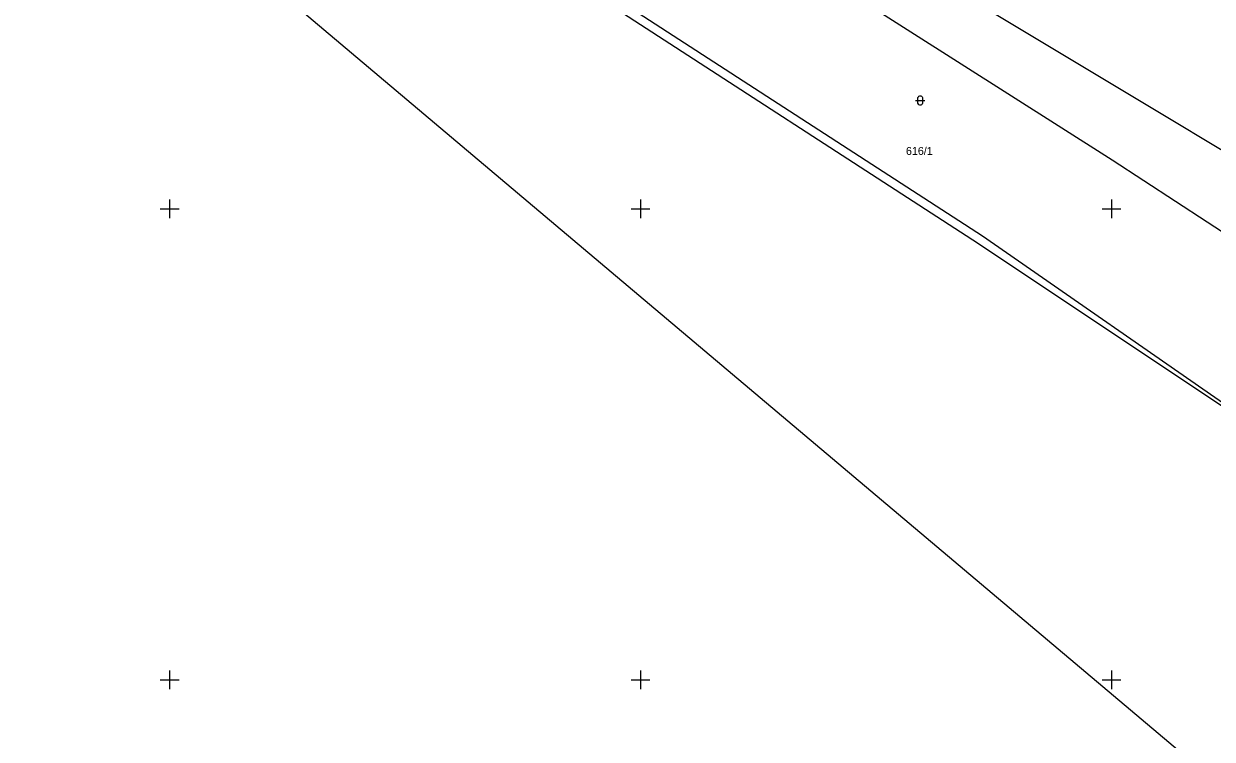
# Model space of a CAD drawing. Extents: x -492379 to -491966, y -1126153 to -1125860.
# Drawn here: x -492309.3 to -492233.6, y -1125993.8 to -1125948.2 of the extents above; entities that cross this region are included whole.
import ezdxf

# ---------------------------------------------------------------- set-up
doc = ezdxf.new("R2010")
doc.units = 0
doc.layers.add('katastrální mapa', color=7, linetype='Continuous')
doc.layers.add('síť', color=7, linetype='Continuous')

msp = doc.modelspace()

# ---------------------------------------------------------------- linework, layer by layer
at = {"layer": 'katastrální mapa'}
for p, q in [((-492309.05, -1125922.31), (-492248.21, -1125961.73)), ((-492309.29, -1125922.78), (-492248.47, -1125962.21)), ((-492281.99, -1125926.77), (-492237.9, -1125953.3)), ((-492283.56, -1125929.15), (-492239.95, -1125956.88)), ((-492225.94, -1126002.74), (-492307.13, -1125934.3)), ((-492252.33, -1125952.92), (-492252.3, -1125952.86)), ((-492252.33, -1125953.28), (-492252.33, -1125952.92)), ((-492252.3, -1125952.86), (-492252.27, -1125952.83)), ((-492252.27, -1125952.83), (-492252.21, -1125952.8)), ((-492252.21, -1125952.8), (-492252.15, -1125952.8)), ((-492252.15, -1125952.8), (-492252.09, -1125952.83)), ((-492252.09, -1125952.83), (-492252.06, -1125952.86)), ((-492252.06, -1125952.86), (-492252.03, -1125952.92)), ((-492252.03, -1125952.92), (-492252.03, -1125953.28)), ((-492252.48, -1125953.1), (-492251.88, -1125953.1)), ((-492252.3, -1125953.34), (-492252.33, -1125953.28)), ((-492252.27, -1125953.37), (-492252.3, -1125953.34)), ((-492252.21, -1125953.4), (-492252.27, -1125953.37)), ((-492252.15, -1125953.4), (-492252.21, -1125953.4)), ((-492252.09, -1125953.37), (-492252.15, -1125953.4)), ((-492252.06, -1125953.34), (-492252.09, -1125953.37)), ((-492252.03, -1125953.28), (-492252.06, -1125953.34)), ((-492237.9, -1125953.3), (-492214.61, -1125967.28)), ((-492239.95, -1125956.88), (-492218.05, -1125971.18)), ((-492248.21, -1125961.73), (-492223.37, -1125978.97)), ((-492248.47, -1125962.21), (-492223.37, -1125978.97))]:
    msp.add_line(p, q, dxfattribs=at)
at = {"layer": 'síť'}
for p, q in [((-492300, -1125959.4), (-492300, -1125960.6)), ((-492270, -1125959.4), (-492270, -1125960.6)), ((-492240, -1125959.4), (-492240, -1125960.6)), ((-492300.6, -1125960), (-492299.4, -1125960)), ((-492270.6, -1125960), (-492269.4, -1125960)), ((-492240.6, -1125960), (-492239.4, -1125960)), ((-492300.6, -1125990), (-492299.4, -1125990)), ((-492300, -1125989.4), (-492300, -1125990.6)), ((-492270.6, -1125990), (-492269.4, -1125990)), ((-492270, -1125989.4), (-492270, -1125990.6)), ((-492240.6, -1125990), (-492239.4, -1125990)), ((-492240, -1125989.4), (-492240, -1125990.6))]:
    msp.add_line(p, q, dxfattribs=at)

# ---------------------------------------------------------------- texts
at = {"layer": 'katastrální mapa'}
msp.add_text('616/1', height=0.51, dxfattribs=at).set_placement((-492253.09, -1125956.57))

doc.saveas('drawing.dxf')
